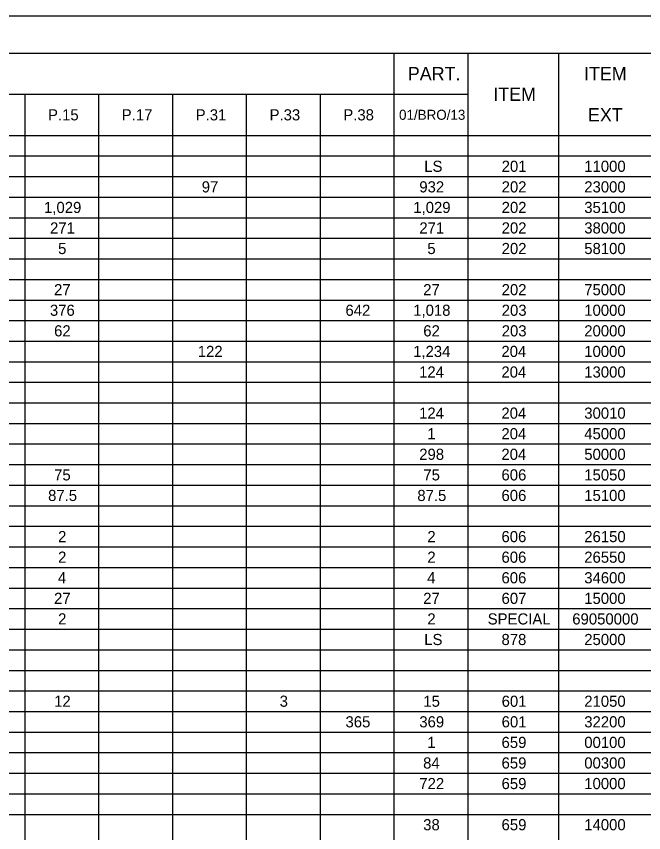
# Model space of a CAD drawing. Extents: x 0 to 34, y 0 to 22.
# Drawn here: x 8.42 to 16.95, y 10.89 to 22 of the extents above; entities that cross this region are included whole.
import ezdxf

# ---------------------------------------------------------------- set-up
doc = ezdxf.new("R2010")
doc.units = 0
for name, color, linetype in [('Default', 7, 'Continuous'), ('SH_Border', 7, 'Continuous'), ('SH_Cut_Line', 7, 'Continuous')]:
    doc.layers.add(name, color=color, linetype=linetype)

msp = doc.modelspace()

# ---------------------------------------------------------------- linework, layer by layer
at = {"layer": 'Default'}
for p, q in [((1.5, 21.5), (32, 21.5)), ((13.555, 21.5), (13.555, 0.502)), ((14.56, 21.5), (14.56, 0.502)), ((15.795, 21.5), (15.795, 0.502)), ((1.5, 20.94), (14.56, 20.94)), ((8.532, 20.94), (8.532, 0.502)), ((9.537, 20.94), (9.537, 0.502)), ((10.541, 20.94), (10.541, 0.502)), ((11.546, 20.94), (11.546, 0.502)), ((12.55, 20.94), (12.55, 0.502)), ((1.5, 20.38), (32, 20.38)), ((1.5, 20.1), (32, 20.1)), ((1.5, 19.82), (32, 19.82)), ((1.5, 19.54), (32, 19.54)), ((1.5, 19.26), (32, 19.26)), ((1.5, 18.98), (32, 18.98)), ((1.5, 18.7), (32, 18.7)), ((1.5, 18.42), (32, 18.42)), ((1.5, 18.14), (32, 18.14)), ((1.5, 17.86), (32, 17.86)), ((1.5, 17.58), (32, 17.58)), ((1.5, 17.3), (32, 17.3)), ((1.5, 17.021), (32, 17.021)), ((1.5, 16.741), (32, 16.741)), ((1.5, 16.461), (32, 16.461)), ((1.5, 16.181), (32, 16.181)), ((1.5, 15.901), (32, 15.901)), ((1.5, 15.621), (32, 15.621)), ((1.5, 15.341), (32, 15.341)), ((1.5, 15.061), (32, 15.061)), ((1.5, 14.781), (32, 14.781)), ((1.5, 14.501), (32, 14.501)), ((1.5, 14.221), (32, 14.221)), ((1.5, 13.941), (32, 13.941)), ((1.5, 13.661), (32, 13.661)), ((1.5, 13.381), (32, 13.381)), ((1.5, 13.101), (32, 13.101)), ((1.5, 12.821), (32, 12.821)), ((1.5, 12.541), (32, 12.541)), ((1.5, 12.261), (32, 12.261)), ((1.5, 11.981), (32, 11.981)), ((1.5, 11.701), (32, 11.701)), ((1.5, 11.421), (32, 11.421)), ((1.5, 11.141), (32, 11.141))]:
    msp.add_line(p, q, dxfattribs=at)
at = {"layer": 'SH_Border'}
msp.add_lwpolyline([(1.5, 21.5), (33.5, 21.5), (33.5, 0.5), (1.5, 0.5)], close=True, dxfattribs=at)
at = {"layer": 'SH_Cut_Line'}
msp.add_lwpolyline([(0, 0), (34, 0), (34, 22), (0, 22)], close=True, dxfattribs=at)

# ---------------------------------------------------------------- texts
at = {"layer": 'Default'}
for s, height, p in [('PART.', 0.1818, (13.744, 21.129)), ('ITEM', 0.1818, (16.141, 21.129)), ('ITEM', 0.1818, (14.906, 20.849)), ('P.15', 0.1515, (8.849, 20.584)), ('P.17', 0.1515, (9.852, 20.584)), ('P.31', 0.1515, (10.858, 20.584)), ('P.33', 0.1515, (11.863, 20.584)), ('P.38', 0.1515, (12.866, 20.584)), ('01/BRO/13', 0.1364, (13.624, 20.592)), ('EXT', 0.1818, (16.195, 20.569)), ('LS', 0.1515, (13.967, 19.884)), ('201', 0.1515, (15.02, 19.884)), ('11000', 0.1515, (16.144, 19.884)), ('97', 0.1515, (10.94, 19.604)), ('932', 0.1515, (13.9, 19.604)), ('202', 0.1515, (15.02, 19.604)), ('23000', 0.1515, (16.144, 19.604)), ('1,029', 0.1515, (8.795, 19.324)), ('1,029', 0.1515, (13.818, 19.324)), ('202', 0.1515, (15.02, 19.324)), ('35100', 0.1515, (16.144, 19.324)), ('271', 0.1515, (8.877, 19.045)), ('271', 0.1515, (13.9, 19.045)), ('202', 0.1515, (15.02, 19.045)), ('38000', 0.1515, (16.144, 19.045)), ('5', 0.152, (8.986, 18.765)), ('5', 0.152, (14.009, 18.765)), ('202', 0.1515, (15.02, 18.765)), ('58100', 0.1515, (16.144, 18.765)), ('27', 0.1515, (8.931, 18.205)), ('27', 0.1515, (13.953, 18.205)), ('202', 0.1515, (15.02, 18.205)), ('75000', 0.1515, (16.144, 18.205)), ('376', 0.1515, (8.875, 17.925)), ('642', 0.1515, (12.895, 17.925)), ('1,018', 0.1515, (13.817, 17.925)), ('203', 0.1515, (15.021, 17.925)), ('10000', 0.1515, (16.144, 17.925)), ('62', 0.1515, (8.932, 17.645)), ('62', 0.1515, (13.954, 17.645)), ('203', 0.1515, (15.021, 17.645)), ('20000', 0.1515, (16.144, 17.645)), ('122', 0.1515, (10.886, 17.365)), ('1,234', 0.1515, (13.816, 17.365)), ('204', 0.1515, (15.017, 17.365)), ('10000', 0.1515, (16.144, 17.365)), ('124', 0.1515, (13.897, 17.085)), ('204', 0.1515, (15.017, 17.085)), ('13000', 0.1515, (16.144, 17.085)), ('124', 0.1515, (13.897, 16.525)), ('204', 0.1515, (15.017, 16.525)), ('30010', 0.1515, (16.144, 16.525)), ('1', 0.152, (14.009, 16.245)), ('204', 0.1515, (15.017, 16.245)), ('45000', 0.1515, (16.144, 16.245)), ('298', 0.1515, (13.899, 15.965)), ('204', 0.1515, (15.017, 15.965)), ('50000', 0.1515, (16.144, 15.965)), ('75', 0.1515, (8.932, 15.685)), ('75', 0.1515, (13.955, 15.685)), ('606', 0.1515, (15.018, 15.685)), ('15050', 0.1515, (16.144, 15.685)), ('87.5', 0.1515, (8.85, 15.405)), ('87.5', 0.1515, (13.873, 15.405)), ('606', 0.1515, (15.018, 15.405)), ('15100', 0.1515, (16.144, 15.405)), ('2', 0.152, (8.986, 14.845)), ('2', 0.152, (14.009, 14.845)), ('606', 0.1515, (15.018, 14.845)), ('26150', 0.1515, (16.144, 14.845)), ('2', 0.152, (8.986, 14.565)), ('2', 0.152, (14.009, 14.565)), ('606', 0.1515, (15.018, 14.565)), ('26550', 0.1515, (16.144, 14.565)), ('4', 0.152, (8.983, 14.285)), ('4', 0.152, (14.006, 14.285)), ('606', 0.1515, (15.018, 14.285)), ('34600', 0.1515, (16.144, 14.285)), ('27', 0.1515, (8.931, 14.005)), ('27', 0.1515, (13.953, 14.005)), ('607', 0.1515, (15.019, 14.005)), ('15000', 0.1515, (16.144, 14.005)), ('2', 0.152, (8.986, 13.725)), ('2', 0.152, (14.009, 13.725)), ('SPECIAL', 0.1515, (14.83, 13.725)), ('69050000', 0.1515, (15.981, 13.725)), ('LS', 0.1515, (13.967, 13.445)), ('878', 0.1515, (15.018, 13.445)), ('25000', 0.1515, (16.144, 13.445)), ('12', 0.1515, (8.932, 12.605)), ('3', 0.152, (12, 12.605)), ('15', 0.1515, (13.955, 12.605)), ('601', 0.1515, (15.02, 12.605)), ('21050', 0.1515, (16.144, 12.605)), ('365', 0.1515, (12.896, 12.325)), ('369', 0.1515, (13.9, 12.325)), ('601', 0.1515, (15.02, 12.325)), ('32200', 0.1515, (16.144, 12.325)), ('1', 0.152, (14.009, 12.045)), ('659', 0.1515, (15.019, 12.045)), ('00100', 0.1515, (16.144, 12.045)), ('84', 0.1515, (13.952, 11.765)), ('659', 0.1515, (15.019, 11.765)), ('00300', 0.1515, (16.144, 11.765)), ('722', 0.1515, (13.9, 11.485)), ('659', 0.1515, (15.019, 11.485)), ('10000', 0.1515, (16.144, 11.485)), ('38', 0.1515, (13.953, 10.925)), ('659', 0.1515, (15.019, 10.925)), ('14000', 0.1515, (16.144, 10.925))]:
    msp.add_text(s, height=height, dxfattribs=at).set_placement(p)

doc.saveas('drawing.dxf')
